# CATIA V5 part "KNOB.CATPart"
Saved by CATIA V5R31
Part number: KNOB
Revision: 01
Nomenclature: KNOB
Source: Unknown
Property "部品番号(B社)": "MOLD111111"
Property "部品名称(B社)": "KNOB"
Property "Version(B社)": "02"
Property "材質(B社)": "PC"
Bounding box of the stored display mesh (mm): x -12.5 to 12.5, y -20.5 to 20.5, z -4 to 13.679
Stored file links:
  \\solize.local\damia\dept\DDE_Design\10_order\2305701_JAMA_変換検証STEP3_お手本モデル作成\work\03_東洋電装_スイッチ\10_CATIA_V5\KNOB.CATPart
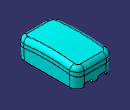
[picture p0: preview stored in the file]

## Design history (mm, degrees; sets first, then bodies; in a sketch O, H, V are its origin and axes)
WSupportSet1
AxisSystem1: origin (0, 0, -8), X (-1, 0, 0), Y (0, -1, 0), Z (0, 0, 1)
Body1 (main body)
  Solid1: solid without history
